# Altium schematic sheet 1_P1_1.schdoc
size 423 x 300 mm
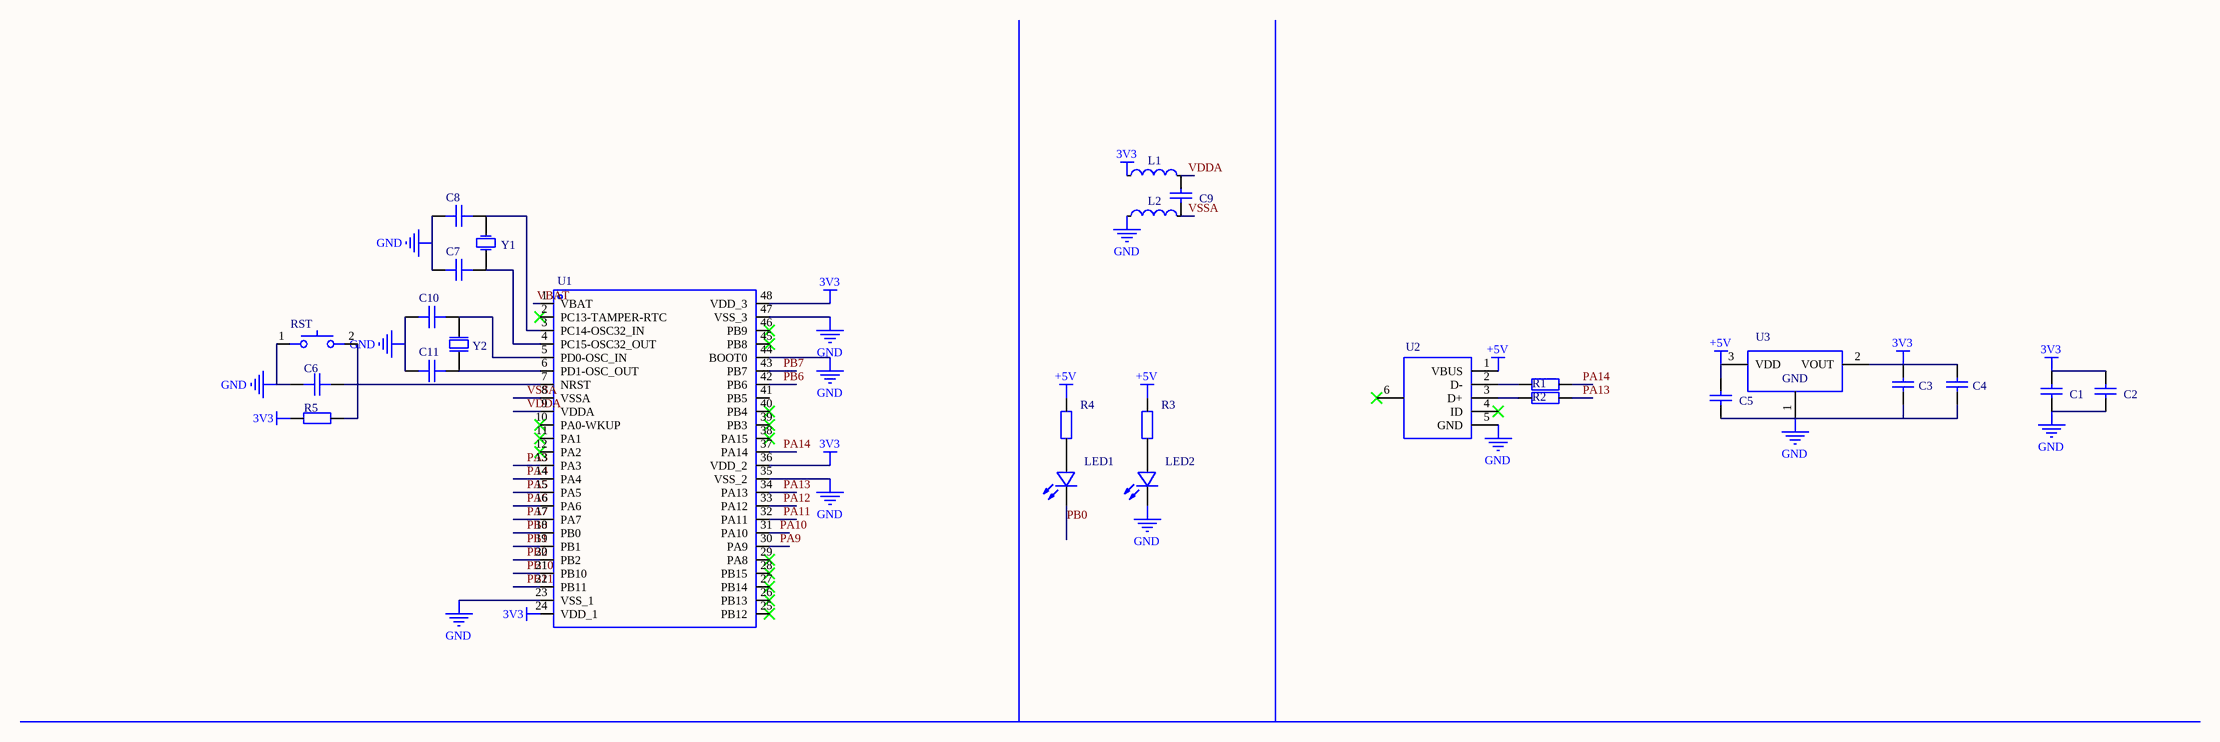
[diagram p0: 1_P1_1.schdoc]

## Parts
C1  (no value)  [c0603_1]
C2  (no value)  [c0603_1]
C3  (no value)  [c0603_1]
C4  (no value)  [c0805]
C5  (no value)  [c0603_1]
C6  (no value)  [c0402_1]
C7  (no value)  [c0402_1]
C8  (no value)  [c0402_1]
C9  (no value)  [c0603_1]
C10  (no value)  [c0402_1]
C11  (no value)  [c0402_1]
L1  (no value)  [l0603]
L2  (no value)  [l0603]
LED1  (no value)  [led0603-r-rd_1]
LED2  (no value)  [led0603-r-rd_1]
R1  (no value)  [r0805]
R2  (no value)  [r0805]
R3  (no value)  [r0805]
R4  (no value)  [r0805]
R5  (no value)  [r0402_1]
RST  (no value)  [sw-smd_l3.9-w3.0-p4.45]
U1  (no value)  [lqfp-48_l7.0-w7.0-p0.50-ls9.0-bl_1]
U2  (no value)  [micro-usb-smd_micro-qtzb5.0]
U3  (no value)  [sot-23-3_l2.9-w1.3-p1.90-ls2.4-br]
Y1  (no value)  [crystal-smd_l2.0-w1.2]
Y2  (no value)  [osc-smd_2p-l3.2-w2.5]

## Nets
3V3: C1.2 C2.2 C3.2 C4.2 L1.1 R5.2 U1.24(VDD_1) U1.36(VDD_2) U1.48(VDD_3) U3.2(VOUT)
+5V: C5.2 R3.2 R4.2 U2.1(VBUS) U3.3(VDD)
GND: C1.1 C2.1 C3.1 C4.1 C5.1 C6.2 C7.2 C8.2 C10.2 C11.2 L2.1 LED2.2(K) RST.1 U1.23(VSS_1) U1.35(VSS_2) U1.44(BOOT0) U1.47(VSS_3) U2.5(GND) U3.1(GND)
PA3: U1.13(PA3)
PA4: U1.14(PA4)
PA5: U1.15(PA5)
PA6: U1.16(PA6)
PA7: U1.17(PA7)
PA9: U1.30(PA9)
PA10: U1.31(PA10)
PA11: U1.32(PA11)
PA12: U1.33(PA12)
PA13: R2.2 U1.34(PA13)
PA14: R1.2 U1.37(PA14)
PB0: LED1.2(K) U1.18(PB0)
PB1: U1.19(PB1)
PB2: U1.20(PB2)
PB6: U1.42(PB6)
PB7: U1.43(PB7)
PB10: U1.21(PB10)
PB11: U1.22(PB11)
VBAT: U1.1(VBAT)
VDDA: C9.2 L1.2 U1.9(VDDA)
VSSA: C9.1 L2.2 U1.8(VSSA)
NetC6_1: C6.1 R5.1 RST.2 U1.7(NRST)
NetC7_1: C7.1 U1.4(PC15-OSC32_OUT) Y1.2(OSC2)
NetC8_1: C8.1 U1.3(PC14-OSC32_IN) Y1.1(OSC1)
NetC10_1: C10.1 U1.5(PD0-OSC_IN) Y2.1(OSC1)
NetC11_1: C11.1 U1.6(PD1-OSC_OUT) Y2.2(OSC2)
NetLED1_1: LED1.1(A) R4.1
NetLED2_1: LED2.1(A) R3.1
NetR1_1: R1.1 U2.2(D-)
NetR2_1: R2.1 U2.3(D+)

Not connected (* = marked no-connect by the designer): U1 2(PC13-TAMPER-RTC)* 10(PA0-WKUP)* 11(PA1)* 12(PA2)* 25(PB12)* 26(PB13)* 27(PB14)* 28(PB15)* 29(PA8)* 38(PA15)* 39(PB3)* 40(PB4)* 41(PB5) 45(PB8)* 46(PB9)*; U2 4(ID)* 6(EH)*

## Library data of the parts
C1-C3 C5 C9 = CGA3E2X7R1H104KT0Y0N: Manufacturer: TDK; Add into BOM: yes; Value: 100nF; Tolerance: ±10%; Voltage Rated: 50V; Temperature Coefficient: X7R; Description: 容值:100nF;精度:±10%;额定电压:50V;温度系数:X7R;
C4 = CL21F105ZOFNNNE: Manufacturer: SAMSUNG(三星); Add into BOM: yes; Value: 1uF; Tolerance: -20%~+80%; Voltage Rated: 16V; Temperature Coefficient: Y5V; Description: 容值:1uF;精度:-20%~+80%;额定电压:16V;温度系数:Y5V;
C6 = 0402B104M250CT: Manufacturer: 华新科(Walsin); Add into BOM: yes; Value: 100nF; Tolerance: ±20%; Voltage Rated: 25V; Temperature Coefficient: X7R; Description: 容值:100nF;精度:±20%;额定电压:25V;温度系数:X7R;
C7 C8 = GRM1552C1H100JA01D: Manufacturer: muRata(村田); Add into BOM: yes; Value: 10pF; Tolerance: ±5%; Voltage Rated: 50V; Temperature Coefficient: CH; Description: 容值:10pF;精度:±5%;额定电压:50V;温度系数:CH;
C10 C11 = CC0402FRNPO9BN200: Manufacturer: YAGEO(国巨); Add into BOM: yes; Value: 20pF; Tolerance: ±1%; Voltage Rated: 50V; Temperature Coefficient: NP0; Description: 容值:20pF;精度:±1%;额定电压:50V;温度系数:NP0;
L1 L2 = FCI1608F-100K: Manufacturer: 台庆; Add into BOM: yes; Value: 10uH; Tolerance: ±10%; Rated Current: 15mA; DC Resistance (DCR): 2.55; Description: 电感值:10uH;精度:±10%;额定电流:15mA;饱和电流(Isat):-;直流电阻(DCR):2.55;
LED1 LED2 = MHT192WDT-CYAN: Manufacturer: MEIHUA(美华科技); Add into BOM: yes; Emitted Color: 青色; Lens Color: 雾状绿; Forward Current: 20mA; Forward Voltage (VF): 3.1V; Luminous Intensity: 900mcd; Power Dissipation: 100mW; Viewing Angle: 130°; Description: 发光颜色:青色;二极管配置:-;透镜颜色:雾状绿;主波长:-;峰值波长:-;色温:-;光通量(25时):-;测试电流:20mA;正向电压(VF):3.1V;发光强度:900mcd;功率:100mW;发光角度:130°;安装方式:-;工作温度:-40~+85;
R1 R2 = AC0805JR-0722RL: Manufacturer: YAGEO(国巨); Add into BOM: yes; Value: 22; Tolerance: ±5%; Power(Watts): 125mW; Temperature Coefficient: ±100ppm/; Overload Voltage (Max): 150V; Description: 电阻类型:厚膜电阻;阻值:22;精度:±5%;功率:125mW;温度系数:±100ppm/;最大工作电压:150V;工作温度范围:-55~+155;
R3 R4 = 0805W8J0511T5E: Manufacturer: UNI-ROYAL(厚声); Add into BOM: yes; Value: 510; Tolerance: ±5%; Power(Watts): 125mW; Temperature Coefficient: ±100ppm/; Overload Voltage (Max): 150V; Description: 电阻类型:厚膜电阻;阻值:510;精度:±5%;功率:125mW;温度系数:±100ppm/;最大工作电压:150V;工作温度范围:-55~+155;
R5 = ERA2AED103X: Manufacturer: PANASONIC(松下); Symbol: era-2aed103x; Add into BOM: yes; Value: 10k; Tolerance: ±0.5%; Power(Watts): 63mW; Temperature Coefficient: ±25ppm/K; Overload Voltage (Max): 50V; Description: 电阻类型:薄膜电阻;阻值:10k;精度:±0.5%;功率:63mW;温度系数:±25ppm/K;最大工作电压:50V;工作温度范围:-55~+155;
RST = SKRKAEE020_1: Manufacturer: ALPSALPINE(阿尔卑斯阿尔派); Add into BOM: yes; Contact Current: 50mA; Voltage Rating (DC): 12V; Circuit: 单刀单掷; Actuator Style: 圆形按钮; Switch Length: 3.9mm; Switch Width: 2.9mm; Switch Height: 2mm; Description: 触点电流:50mA;额定电压(DC):12V;电路结构:单刀单掷;安装方式:立贴;按钮形状:圆形按钮;带灯:-;开关长度:3.9mm;开关宽度:2.9mm;开关高度:2mm;
U1 = STM32F103C8T6_2: Manufacturer: ST(意法半导体); Add into BOM: yes; Speed: 72MHz; Voltage - Supply (Vcc/Vdd): 2V ~ 3.6V; Program Memory Size: 64KB; RAM Size: 20KB; Number of I/O: 37; A/D: 10x12bit; PWM: 13; UART/USART: 3 USART; I2C（SMBUS/PMBUS）: 2; USB Device: 1; Description: 主频（MAX):72MHz;工作电压:2V ~ 3.6V;
U2 = MICRO QTZB5.0 (040): Add into BOM: yes
U3 = SC662K-3.3V: Manufacturer: FM富满; Add into BOM: yes; Output Type: 固定; Output Polarity: 正; Number of Outputs: 1; Maximum Input Voltage: 6V; Output Voltage: 3.3V; Dropout Voltage: 38mV@(10mA); Output Current: 250mA; Power Supply Rejection Ratio (PRSS): 50dB@(1kHz); Description: 输出类型:固定;输出极性:正;输出通道数:1;最大输入电压:6V;输出电压:3.3V;压差:38mV@(10mA);输出电流:250mA;电源纹波抑制比(PRSS):50dB@(1kHz);; NAME: GND
Y1 = TFX-03-32.768K: Manufacturer: RIVER(大河); Add into BOM: yes; Description: 晶振类型:-;频率:-;频率公差:-;频率稳定度:-;负载电容:-;工作温度:-;
Y2 = 1ZCM08000EK0A: Manufacturer: KDS大真空; Add into BOM: yes; Description: 晶振类型:-;频率:-;频率公差:-;频率稳定度:-;负载电容:-;工作温度:-;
